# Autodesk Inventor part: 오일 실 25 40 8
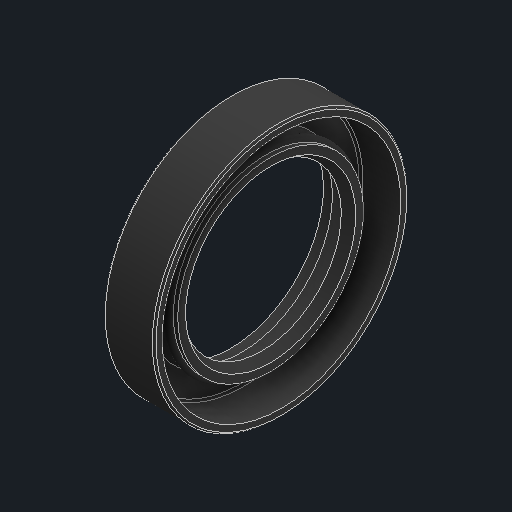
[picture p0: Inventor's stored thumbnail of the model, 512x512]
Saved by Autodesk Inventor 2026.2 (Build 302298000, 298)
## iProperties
Created: 2025-11
Part Number: 오일 실 25 40 8
Material: 고무
Description: 오일-실
Document SubType Name: Modeling
Designer: PC2-07
Density: 0.93 g/cm^3
Appearance: 기본값
Author: jhkim
Sending System: Autodesk Inventor 2026
Preprocessor: ST-DEVELOPER v20.1
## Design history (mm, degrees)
feature "Solid1"
node "솔리드1"
